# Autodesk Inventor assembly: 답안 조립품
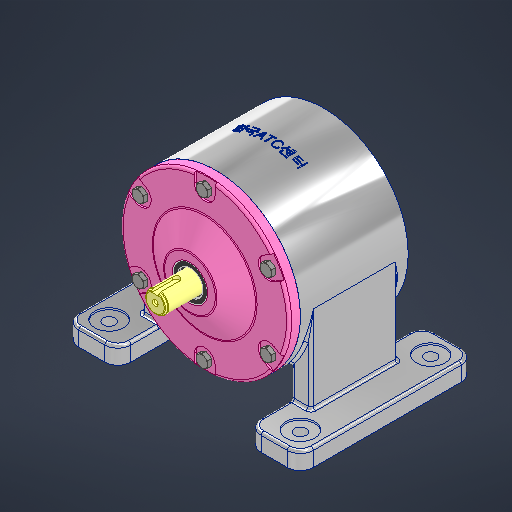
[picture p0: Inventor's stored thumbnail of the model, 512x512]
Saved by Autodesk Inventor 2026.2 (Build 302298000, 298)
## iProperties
Created: 2025-12
Part Number: 답안 조립품
Document SubType Name: Assembly
Designer: PC2-07
Author: PC2-07
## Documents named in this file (17)
- C:\Users\PC2-07\Desktop\751203V1016\답안 조립품.iam
- C:\Users\PC2-07\Desktop\751203V1016\본체.ipt
- C:\Users\PC2-07\Desktop\751203V1016\6각 머리 볼트 M8x20\6각 머리 볼트 M8x20.ipt
- C:\Users\PC2-07\Desktop\751203V1016\C형 멈춤링 구멍용 42\C형 멈춤링 구멍용 42.ipt
- C:\Users\PC2-07\Desktop\751203V1016\구동 기어\구동 기어.ipt
- C:\Users\PC2-07\Desktop\751203V1016\기어 축\기어 축.ipt
- C:\Users\PC2-07\Desktop\751203V1016\깊은 홈 볼 베어링 6004\깊은 홈 볼 베어링 6004.ipt
- C:\Users\PC2-07\Desktop\751203V1016\깊은 홈 볼 베어링 6005\깊은 홈 볼 베어링 6005.ipt
- C:\Users\PC2-07\Desktop\751203V1016\엔드 캡\엔드 캡.ipt
- C:\Users\PC2-07\Desktop\751203V1016\오일 실 25 40 8\오일 실 25 40 8.ipt
- C:\Users\PC2-07\Desktop\751203V1016\종동 기어\종동 기어.ipt
- C:\Users\PC2-07\Desktop\751203V1016\출력 축\출력 축.ipt
- C:\Users\PC2-07\Desktop\751203V1016\칼라 1\칼라 1.ipt
- C:\Users\PC2-07\Desktop\751203V1016\칼라 2\칼라 2.ipt
- C:\Users\PC2-07\Desktop\751203V1016\커버\커버.ipt
- C:\Users\PC2-07\Desktop\751203V1016\평행 키 6x6x16\평행 키 6x6x16.ipt
- C:\Users\PC2-07\Desktop\751203V1016\6각 구멍붙이 볼트 M4x10\6각 구멍붙이 볼트 M4x10.ipt
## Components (9 placed, 4 different names)
1. 6각 머리 볼트 M8x20:1
2. C형 멈춤링 구멍용 42:1
3. 구동 기어:1 — 각도:2
4. 6각 구멍붙이 볼트 M4x10:1
5. 6각 머리 볼트 M8x20:2
6. 6각 머리 볼트 M8x20:3
7. 6각 머리 볼트 M8x20:4
8. 6각 머리 볼트 M8x20:5
9. 6각 머리 볼트 M8x20:6
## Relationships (1: Angle 1)
- 각도:2 [Angle]: 구동 기어:1
